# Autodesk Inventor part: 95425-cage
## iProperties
Author: Administrator
Shininess: 64.0
Angle Display Precision: 2
Document Length Units: 11272
Document Angle Units: 11286
Document Time Units: 11279
Document Mass Units: 11290
Document Length Units Precision: 3
Document Angle Units Precision: 2
Compacted: True
PropertySet Name: _Private Model Information
Created: 2002-04
Part Number: 95425-cage
Material: ASTM A36 HRS
Document SubType Name: Modeling
Designer: Administrator
Control State: 0
Master: False
Checked Out: False
PropertySet Name: Design Tracking Control
Density: 0.0
Volumn: 0.0
Area: 0.0
PropertySet Name: Model Information
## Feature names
1. Revolution1
2. Extrusion1
3. Circular Pattern1
